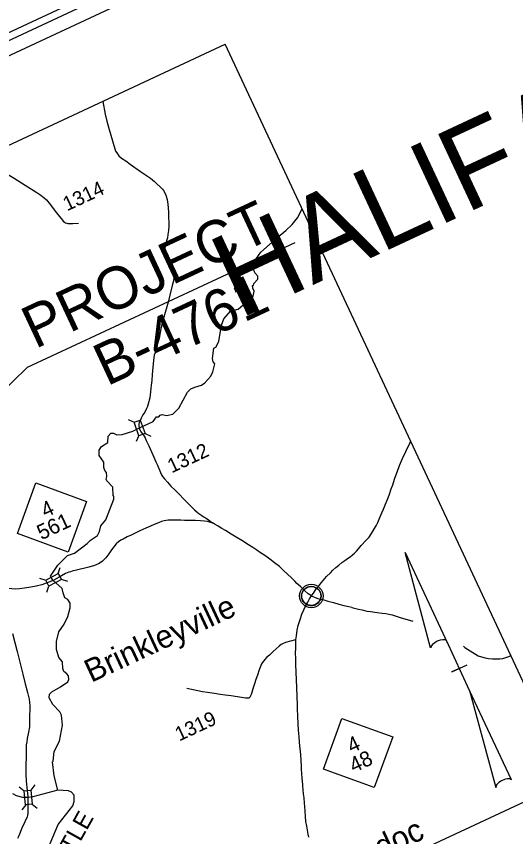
# Model space of a CAD drawing. Extents: x 2318983 to 2324558, y 920396 to 924651.
# Drawn here: x 2320803 to 2321231, y 922780 to 923483 of the extents above; entities that cross this region are included whole.
import ezdxf

# ---------------------------------------------------------------- set-up
doc = ezdxf.new("R2010")
doc.units = 0
for name, color, linetype in [('Default', 7, 'Continuous'), ('Exist Civil Demographics City Label', 7, 'Continuous'), ('Exist Civil Demographics Community CELL', 7, 'Continuous'), ('Exist Hydrographic Creek Single Shore', 7, 'Continuous'), ('Exist Road Primary NC Attributed', 7, 'Continuous'), ('Exist Road Primary NC Shield CELL', 7, 'Continuous'), ('Exist Road Primary NC Shield Number Label', 7, 'Continuous'), ('Exist Road Primary NC Structure Standard Bridge CELL', 7, 'Continuous'), ('Exist Road Secondary Structure Standard Bridge CELL', 7, 'Continuous'), ('Exist Road Secondary Type 20 Attributed', 7, 'Continuous'), ('Exist Road Secondary Type 41 Attributed', 7, 'Continuous'), ('Exist Road Secondary Type 51 Attributed', 7, 'Continuous'), ('Exist Road Secondary Type 51 Number Label', 7, 'Continuous'), ('Pattern 3', 7, 'Continuous'), ('Prop North Arrow for Plan Sheets CELL', 7, 'Continuous'), ('Sheet Data Field CELL', 7, 'Continuous'), ('Sheet Plot Border Inside CELL', 7, 'Continuous'), ('Sheet Title CELL', 7, 'Continuous')]:
    doc.layers.add(name, color=color, linetype=linetype)

msp = doc.modelspace()

# ---------------------------------------------------------------- linework, layer by layer
at = {"layer": 'Exist Civil Demographics Community CELL'}
msp.add_lwpolyline([(2321047.37, 922987.36), (2321047.47, 922987.95), (2321047.66, 922988.65), (2321047.97, 922989.42), (2321048.28, 922990.03), (2321048.64, 922990.64), (2321049.03, 922991.18), (2321049.46, 922991.65), (2321049.94, 922992.14), (2321050.53, 922992.62), (2321051.11, 922993.01), (2321051.63, 922993.32), (2321052.17, 922993.58), (2321052.75, 922993.82), (2321053.34, 922994.02), (2321053.8, 922994.14), (2321054.32, 922994.22), (2321054.76, 922994.29), (2321055.43, 922994.32), (2321055.91, 922994.31), (2321056.51, 922994.28), (2321057.03, 922994.21), (2321057.55, 922994.1), (2321058.08, 922993.95), (2321058.63, 922993.74), (2321059.34, 922993.43), (2321060, 922993.06), (2321060.54, 922992.69), (2321061.09, 922992.26), (2321061.44, 922991.93), (2321061.88, 922991.46), (2321062.29, 922990.96), (2321062.62, 922990.47), (2321062.95, 922989.94), (2321063.21, 922989.39), (2321063.43, 922988.86), (2321063.6, 922988.33), (2321063.73, 922987.84), (2321063.85, 922987.2), (2321063.91, 922986.7), (2321063.94, 922986.06), (2321063.92, 922985.44), (2321063.86, 922984.84), (2321063.76, 922984.26), (2321063.59, 922983.6), (2321063.39, 922982.98), (2321063.14, 922982.44), (2321062.81, 922981.8), (2321062.46, 922981.24), (2321062.09, 922980.74), (2321061.64, 922980.23), (2321061.08, 922979.71), (2321060.55, 922979.27), (2321060.02, 922978.9), (2321059.56, 922978.64), (2321058.83, 922978.29), (2321058.07, 922978.01), (2321057.44, 922977.85), (2321056.74, 922977.71), (2321056.27, 922977.66), (2321055.79, 922977.63), (2321055.2, 922977.63), (2321054.74, 922977.68), (2321054.14, 922977.76), (2321053.51, 922977.89), (2321053.03, 922978.03), (2321052.48, 922978.23), (2321051.99, 922978.44), (2321051.57, 922978.68), (2321050.85, 922979.11), (2321050.26, 922979.57), (2321049.73, 922980.05), (2321049.26, 922980.56), (2321048.92, 922980.98), (2321048.61, 922981.43), (2321048.17, 922982.18), (2321047.99, 922982.56), (2321047.8, 922982.99), (2321047.53, 922983.86), (2321047.37, 922984.61), (2321047.29, 922985.15), (2321047.26, 922985.83), (2321047.25, 922986.32), (2321047.31, 922987.01)], close=True, dxfattribs=at)
for centre, radius in [((2321055.62, 922986.04), 10.03), ((2321055.59, 922986.07), 8.15)]:
    msp.add_circle(centre, radius, dxfattribs=at)
at = {"layer": 'Exist Hydrographic Creek Single Shore'}
for points in [[(2321006.2, 923272.57), (2321012.45, 923281.07), (2321027.04, 923294.35), (2321033.75, 923299.55), (2321039.22, 923304.94), (2321043.67, 923310.54), (2321047.65, 923318.13), (2321047.69, 923318.3)], [(2321006.03, 923252.46), (2321006.2, 923254.32), (2321009.87, 923257.87), (2321009.81, 923260.53), (2321007.13, 923263.33), (2321005.63, 923267.22), (2321006.2, 923272.57)], [(2320972.05, 923198.57), (2320973.65, 923199.6), (2320976.25, 923204.56), (2320978.57, 923218.3), (2320980.54, 923223.87), (2320986.42, 923230.33), (2320992.74, 923232.04), (2321005.73, 923243.24), (2321006.49, 923247.55), (2321005.44, 923250.17), (2321005.21, 923252.42), (2321006.03, 923252.46)], [(2320955.83, 923165.36), (2320961.35, 923167.04), (2320964.2, 923168.93), (2320969.46, 923174.56), (2320971.26, 923178.43), (2320972.81, 923185.27), (2320971.36, 923187.07), (2320970.92, 923189.72), (2320972.05, 923198.57)], [(2320924.98, 923139.78), (2320925.99, 923141.19), (2320927.62, 923141.67), (2320931.53, 923140.86), (2320936.84, 923141.96), (2320941.91, 923147.34), (2320949.31, 923160.81), (2320952.17, 923163.91), (2320955.83, 923165.36)], [(2320902.99, 923127.65), (2320908.3, 923130.23), (2320919.91, 923135.86), (2320922.94, 923139.78), (2320924.98, 923139.78)], [(2320879.71, 923086.24), (2320880.11, 923088.67), (2320879.86, 923091.97), (2320878.41, 923093.61), (2320877.77, 923096.41), (2320877.72, 923100.93), (2320873.56, 923106.65), (2320873.71, 923111.19), (2320875.72, 923114.26), (2320881.21, 923117.79), (2320881.36, 923123.13), (2320883.79, 923125.81), (2320885.84, 923125.65), (2320888.94, 923124.25), (2320893.44, 923124.67), (2320902.5, 923127.5), (2320902.99, 923127.65)], [(2320863.5, 923031.14), (2320866.13, 923033.99), (2320872.23, 923037.96), (2320874.05, 923041.5), (2320875.01, 923046.23), (2320879.49, 923051.34), (2320886.26, 923069.06), (2320886.23, 923071.56), (2320885.62, 923072.1), (2320885.32, 923079.52), (2320880.35, 923084.81), (2320879.71, 923086.24)], [(2320846.06, 922919.22), (2320843.37, 922921.2), (2320842.51, 922923.68), (2320842.24, 922929.64), (2320839.14, 922933.31), (2320837.22, 922940.01), (2320837.15, 922947.03), (2320839.09, 922955.19), (2320843.54, 922961.83), (2320846.74, 922968.43), (2320848.93, 922975.78), (2320848.69, 922979.73), (2320846.79, 922982.97), (2320844.33, 922984.56), (2320842.83, 922988.86), (2320841.96, 922992.39), (2320834.03, 922999.56), (2320832.05, 923002.92), (2320838.28, 923012.42), (2320846.4, 923020.9), (2320852.53, 923022.77), (2320863.5, 923031.14)], [(2320834.15, 922844.27), (2320835.08, 922852.47), (2320839.71, 922861.54), (2320842.22, 922875.29), (2320841.31, 922883.89), (2320839.83, 922886.58), (2320834.02, 922892.88), (2320830.9, 922898.73), (2320831.07, 922901.64), (2320833.09, 922903.9), (2320840.64, 922908.09), (2320846.74, 922912.46), (2320847.73, 922914.36), (2320847.51, 922917.58), (2320846.06, 922919.22)], [(2320838.11, 922819.31), (2320835.08, 922831.79), (2320833.73, 922843.69), (2320834.15, 922844.27)], [(2320838.11, 922819.31), (2320816.88, 922813.61), (2320814.92, 922813.32), (2320812.16, 922813.1), (2320809.89, 922812.97), (2320808.25, 922813.16), (2320802.9, 922814.4), (2320799.61, 922816.28)], [(2320820.96, 922750.14), (2320821.58, 922753.55), (2320828.2, 922767.39), (2320829.43, 922768.16), (2320838.41, 922790.01), (2320851.15, 922805.96), (2320852.36, 922809.81), (2320852.28, 922814.97), (2320850.02, 922817.62), (2320847.34, 922818.97), (2320838.11, 922819.31)]]:
    msp.add_lwpolyline(points, dxfattribs=at)
at = {"layer": 'Exist Road Primary NC Attributed'}
for points in [[(2321055.62, 922986.04), (2321056.73, 922987.45), (2321058.13, 922989.43), (2321059.79, 922992.04), (2321062.29, 922994.99), (2321064.24, 922997.56), (2321065.83, 922999.45), (2321067.09, 923001.07), (2321068.66, 923002.8), (2321071.95, 923005.91), (2321074.05, 923008.07), (2321076.56, 923010.34), (2321079.08, 923012.5), (2321081.83, 923014.9), (2321084.47, 923016.56), (2321086.67, 923018.06), (2321088.91, 923019.71), (2321090.81, 923021.21), (2321092.71, 923022.86), (2321094.31, 923024.55), (2321096.06, 923026.49), (2321098.48, 923029.27), (2321102.71, 923033.9), (2321105.13, 923036.64), (2321107.11, 923039.61), (2321109.67, 923043.87), (2321111.46, 923046.94), (2321112.61, 923049.17), (2321114.33, 923053.27), (2321116.15, 923057.28), (2321117.49, 923060.44), (2321119.3, 923064.85), (2321120.73, 923068.14), (2321122.35, 923072.64), (2321122.63, 923073.47), (2321124.14, 923077.91), (2321125.51, 923081.35), (2321127.02, 923086.24), (2321128.17, 923089.47), (2321129.4, 923093.11), (2321131.36, 923097.95), (2321133.92, 923104.11), (2321136.71, 923110.07), (2321139.95, 923117.08), (2321140.84, 923118.7)], [(2320971.51, 923048.64), (2320968.21, 923049.45), (2320966.48, 923049.92), (2320963.93, 923050.14), (2320960.68, 923050.49), (2320956.19, 923050.78), (2320951.42, 923050.87), (2320946.89, 923050.91), (2320943.59, 923051.02), (2320935.92, 923051.23), (2320932.73, 923051.09), (2320929.53, 923050.56), (2320927.23, 923049.94), (2320924.49, 923048.78), (2320920.96, 923047.36), (2320917.68, 923045.89), (2320913.72, 923044.17), (2320908.63, 923041.89), (2320903.5, 923039.45), (2320901.05, 923038.29), (2320897.81, 923036.85), (2320894.34, 923034.92), (2320892.12, 923033.93), (2320890.17, 923032.5), (2320888.3, 923030.78), (2320884.25, 923025.76), (2320881.89, 923022.1), (2320879.27, 923018.82), (2320876.6, 923015.89), (2320874.55, 923014.54), (2320873.03, 923013.58), (2320871.74, 923013.05), (2320869.57, 923012.23), (2320864.93, 923010.88), (2320854.29, 923008.14), (2320850.47, 923007.24), (2320848.97, 923006.79), (2320847.78, 923006.49), (2320844.86, 923005.37), (2320839.39, 923002.3), (2320834.67, 922999.67), (2320831.33, 922998.26)], [(2321055.62, 922986.04), (2321054.37, 922986.91), (2321053.01, 922987.94), (2321049.8, 922990.66), (2321046.51, 922993.77), (2321043.28, 922996.83), (2321041.34, 922998.77), (2321039.65, 923000.38), (2321038.25, 923001.84), (2321035.56, 923004.46), (2321031.54, 923008.3), (2321028.2, 923011.31), (2321024.13, 923014.51), (2321020.11, 923017.7), (2321017.67, 923019.39), (2321014.95, 923021.28), (2321012.07, 923023.17), (2321008.95, 923025.34), (2321005.57, 923027.52), (2321001.66, 923029.93), (2320995.91, 923033.55), (2320991.1, 923036.59), (2320986.93, 923039.2), (2320982.08, 923042.14), (2320978.81, 923044.07), (2320975.68, 923045.9), (2320973.16, 923047.49), (2320971.51, 923048.64)], [(2320831.33, 922998.26), (2320828.3, 922996.98), (2320824.41, 922995.55), (2320819.54, 922994.43), (2320815.04, 922993.68), (2320809.58, 922992.78), (2320805.23, 922992.03), (2320801.71, 922991.95), (2320796.02, 922992.33), (2320789.45, 922992.87)], [(2321042.39, 922948.31), (2321042.84, 922951.86), (2321043.57, 922956.64), (2321044.31, 922960.68), (2321045.06, 922963.35), (2321046.2, 922966.85), (2321047.54, 922970.32), (2321049.26, 922974.27), (2321050.75, 922977.39), (2321052.48, 922980.85), (2321054.08, 922983.62), (2321055.62, 922986.04)], [(2321055.62, 922986.04), (2321056.79, 922985.6), (2321058.29, 922985.02), (2321060.26, 922984.29), (2321063.17, 922983.44), (2321066.43, 922982.59), (2321069.83, 922981.7), (2321074.67, 922980.33), (2321079.06, 922979.15), (2321083.4, 922977.98), (2321087.76, 922977.04), (2321090.34, 922976.32), (2321090.27, 922976.24), (2321092.63, 922975.63), (2321096.19, 922974.74), (2321099.35, 922974.04), (2321103.24, 922973.15), (2321106.4, 922972.6), (2321111.96, 922971.78), (2321116.45, 922971.24), (2321119.55, 922970.89), (2321122.22, 922970.33), (2321124.83, 922969.72), (2321131.79, 922967.49), (2321142.65, 922964.35)], [(2321053.38, 922779.17), (2321052.78, 922781.53), (2321051.64, 922788.44), (2321051, 922792.62), (2321050.61, 922796.75), (2321050.29, 922801.25), (2321050.03, 922805.27), (2321049.83, 922808.14), (2321049.33, 922812.76), (2321048.95, 922816.22), (2321048.56, 922819.64), (2321048.27, 922823.09), (2321048.24, 922824.16), (2321047.85, 922829.62), (2321047.61, 922833.61), (2321047.32, 922837.09), (2321047.19, 922839.75), (2321046.8, 922845.23), (2321046.5, 922849.6), (2321046.22, 922852.82), (2321045.88, 922857.07), (2321045.54, 922860.96), (2321045.23, 922865.28), (2321044.71, 922870.96), (2321044.36, 922876.42), (2321044.1, 922882.99), (2321043.88, 922889.19), (2321043.88, 922893.04), (2321043.44, 922899.55), (2321043.07, 922907.69), (2321042.95, 922913.74), (2321042.67, 922921.01), (2321042.45, 922926.87), (2321042.38, 922932.42), (2321042.18, 922937), (2321042.23, 922941.18), (2321042.27, 922945.71), (2321042.39, 922948.31)], [(2321186.11, 922942.87), (2321187.16, 922941.93), (2321198.61, 922934.79), (2321201.42, 922933.89), (2321204.63, 922932.95), (2321207.64, 922932.49), (2321211.04, 922932.09), (2321212.78, 922931.98), (2321214.38, 922931.98), (2321214.87, 922932.04), (2321217.14, 922932.06), (2321219.84, 922932.39), (2321222.39, 922933.21), (2321224.93, 922934.13), (2321226.6, 922934.95)]]:
    msp.add_lwpolyline(points, dxfattribs=at)
at = {"layer": 'Exist Road Primary NC Shield CELL'}
for p, q in [((2320803.5, 923039.53), (2320819.34, 923083.09)), ((2320819.34, 923083.09), (2320862.9, 923067.25)), ((2320862.9, 923067.25), (2320847.06, 923023.7)), ((2320847.06, 923023.7), (2320803.5, 923039.53)), ((2321066.06, 922837.39), (2321081.9, 922880.95)), ((2321081.9, 922880.95), (2321125.46, 922865.11)), ((2321125.46, 922865.11), (2321109.62, 922821.55)), ((2321109.62, 922821.55), (2321066.06, 922837.39))]:
    msp.add_line(p, q, dxfattribs=at)
at = {"layer": 'Exist Road Primary NC Structure Standard Bridge CELL'}
for p, q in [((2320838.6, 923005.31), (2320840.25, 923010.62)), ((2320822.48, 923001.3), (2320827.8, 922999.65)), ((2320841.2, 923000.38), (2320846.52, 922998.73)), ((2320828.8, 922989.28), (2320830.45, 922994.6))]:
    msp.add_line(p, q, dxfattribs=at)
msp.add_lwpolyline([(2320827.8, 922999.65), (2320838.59, 923005.33), (2320841.24, 923000.29), (2320830.45, 922994.6)], close=True, dxfattribs=at)
at = {"layer": 'Exist Road Secondary Structure Standard Bridge CELL'}
for p, q in [((2320911.35, 923142.05), (2320908.97, 923137.01)), ((2320898.57, 923137.48), (2320903.6, 923135.1)), ((2320907.8, 923123.64), (2320905.42, 923118.61)), ((2320913.05, 923125.52), (2320918.08, 923123.13)), ((2320818.45, 922823.84), (2320814.97, 922819.5)), ((2320804.96, 922822.36), (2320809.3, 922818.88)), ((2320810.73, 922806.77), (2320807.25, 922802.42)), ((2320816.27, 922807.37), (2320820.61, 922803.89))]:
    msp.add_line(p, q, dxfattribs=at)
for points in [[(2320908.97, 923137.01), (2320913.07, 923125.53), (2320907.71, 923123.61), (2320903.6, 923135.1)], [(2320814.97, 922819.5), (2320816.3, 922807.37), (2320810.63, 922806.75), (2320809.3, 922818.88)]]:
    msp.add_lwpolyline(points, close=True, dxfattribs=at)
at = {"layer": 'Exist Road Secondary Type 20 Attributed'}
msp.add_lwpolyline([(2321042.39, 922948.31), (2321040.8, 922948.13), (2321038.92, 922947.69), (2321036.57, 922946.99), (2321034.52, 922946.43), (2321033.51, 922945.99), (2321030.94, 922944.94), (2321029.69, 922944.31), (2321027.92, 922942.93), (2321025.51, 922940.63), (2321022.91, 922938.32), (2321019.68, 922935.35), (2321017.19, 922933.13), (2321015.66, 922931.55), (2321014.53, 922930.24), (2321013.39, 922928.58), (2321012.69, 922927.36), (2321011.91, 922925.53), (2321010.77, 922922.64), (2321009.33, 922918.06), (2321008.11, 922914.39), (2321006.89, 922910.63), (2321005.45, 922906.38), (2321004.53, 922903.19), (2321003.92, 922901.48), (2321003.46, 922900.22), (2321003.08, 922899.48), (2321002.64, 922898.89), (2321002.26, 922898.45), (2321001.74, 922898.27), (2321000.6, 922898.34), (2320999.03, 922898.43), (2320992.44, 922899.43), (2320990.28, 922899.83), (2320986.81, 922900.29), (2320981.84, 922900.95), (2320977.38, 922901.6), (2320972.54, 922902.36), (2320966.52, 922903.08), (2320962.2, 922903.86), (2320954.41, 922905.37), (2320948.84, 922906.62)], dxfattribs=at)
at = {"layer": 'Exist Road Secondary Type 41 Attributed'}
msp.add_lwpolyline([(2320876.8, 923410.5), (2320878.78, 923399.48), (2320880.34, 923393.61), (2320882.36, 923386.46), (2320885.01, 923376.74), (2320887.76, 923367.85), (2320888.71, 923366.25), (2320890.66, 923363.62), (2320892.89, 923361.77), (2320896.65, 923359.37), (2320900.27, 923356.61), (2320909.16, 923350.16), (2320913.52, 923347.34), (2320917.62, 923344.45), (2320921.06, 923341.75), (2320927.98, 923335.23), (2320928.87, 923334.11), (2320930.38, 923331.56), (2320930.93, 923329.97), (2320931.98, 923326.16), (2320932.46, 923322.34), (2320932.99, 923315.61), (2320933.25, 923310.25), (2320933.45, 923307.29), (2320933.28, 923303.34), (2320933, 923299.67), (2320932.66, 923296.12), (2320932.15, 923293.24), (2320931.53, 923290.7), (2320930.91, 923288.33), (2320929.59, 923283.5), (2320929.11, 923281.05), (2320929.11, 923279.59), (2320929.33, 923277.84), (2320930.22, 923275.58), (2320931.42, 923273.35), (2320932.83, 923270.98), (2320936.55, 923265.76), (2320937.4, 923263.53), (2320937.73, 923261.76), (2320937.79, 923261.28), (2320937.74, 923259.27), (2320937.28, 923256.45), (2320936.27, 923252.45), (2320934.3, 923244.32), (2320932.72, 923238.23), (2320929.11, 923225.36), (2320927.47, 923218.99), (2320926.68, 923215.15), (2320925.24, 923207.14), (2320923.13, 923200.31), (2320921.84, 923195.68), (2320920.88, 923192.61), (2320920.2, 923188.32), (2320919.13, 923176.13), (2320918.84, 923170.91), (2320918.28, 923166.91), (2320917.66, 923161.09), (2320917.27, 923158.61), (2320916.99, 923156.07), (2320916.61, 923154.18), (2320916.25, 923152.8), (2320915.01, 923148.62), (2320914.29, 923146.85), (2320912.7, 923143.83), (2320911.18, 923141.4), (2320909.68, 923138.57), (2320907.91, 923135), (2320907.57, 923133.59), (2320907.69, 923132.11), (2320908.26, 923129.26)], dxfattribs=at)
at = {"layer": 'Exist Road Secondary Type 51 Attributed'}
for points in [[(2320793.54, 923348.78), (2320800.65, 923344.5), (2320810.3, 923338.55), (2320820.15, 923332.15), (2320823.7, 923329.91), (2320826.63, 923327.79), (2320828.46, 923326.12), (2320830.86, 923323.06), (2320837.01, 923314.83), (2320842.14, 923308.51), (2320842.92, 923307.62), (2320843.98, 923306.8), (2320844.75, 923306.31), (2320846.05, 923305.87), (2320846.79, 923305.74), (2320848.21, 923305.7), (2320851.1, 923305.7), (2320855.87, 923305.87)], [(2320817.04, 923334.18), (2320820.15, 923332.15), (2320823.7, 923329.91), (2320826.63, 923327.79), (2320828.46, 923326.12), (2320830.86, 923323.06), (2320837.01, 923314.83), (2320842.14, 923308.51), (2320842.92, 923307.62), (2320843.98, 923306.8), (2320844.75, 923306.31), (2320846.05, 923305.87), (2320846.79, 923305.74), (2320848.21, 923305.7), (2320851.1, 923305.7), (2320855.87, 923305.87)], [(2320908.26, 923129.26), (2320909.71, 923126.7), (2320911.63, 923123.94), (2320912.7, 923122.19), (2320912.74, 923122.11)], [(2320912.7, 923122.19), (2320914.05, 923119.54), (2320916.31, 923114.94), (2320919.69, 923107.24), (2320922.34, 923101.2), (2320923.58, 923098.38), (2320926.18, 923091.94), (2320927.02, 923090.08), (2320928.09, 923088.45), (2320929.62, 923086.53), (2320932.13, 923083.7), (2320935.2, 923080.41), (2320938.91, 923076.79), (2320942.05, 923073.63), (2320946.42, 923069.09), (2320950.87, 923064.44), (2320955.33, 923060.04), (2320957.78, 923057.93), (2320959.16, 923056.88), (2320961.78, 923055.07), (2320963.81, 923053.8), (2320964.86, 923053.14), (2320967.03, 923051.77), (2320968.97, 923050.33), (2320971.51, 923048.64)], [(2320799.33, 922953.77), (2320803.38, 922938.26), (2320806.13, 922926.86), (2320808.12, 922919.07), (2320810.22, 922910.57), (2320812.12, 922903.13), (2320813.62, 922897.53), (2320814.26, 922891.88), (2320814.11, 922888.49), (2320814.01, 922883.49), (2320814.06, 922876.09), (2320813.91, 922873.69), (2320813.07, 922869.2), (2320812.02, 922863.65), (2320811.52, 922860.9), (2320811.17, 922858.4), (2320810.97, 922856.5), (2320810.97, 922849.06), (2320810.77, 922839.66), (2320810.87, 922833.04), (2320811.19, 922827.18), (2320811.8, 922819.09), (2320812.52, 922814.14)], [(2320812.52, 922814.14), (2320812.6, 922802.18), (2320812.52, 922799.59), (2320812.27, 922797.61), (2320811.92, 922796.41), (2320809.97, 922792.32), (2320807.42, 922786.82), (2320804.83, 922780.32), (2320803.63, 922777.88)]]:
    msp.add_lwpolyline(points, dxfattribs=at)
at = {"layer": 'Pattern 3'}
for p, q in [((2320106.71, 923051.1), (2320981.79, 923459.5)), ((2321276.76, 922827.48), (2320981.79, 923459.5)), ((2320812.16, 923182.33), (2321041.74, 923289.48)), ((2320812.16, 923182.33), (2320687.87, 923062.03))]:
    msp.add_line(p, q, dxfattribs=at)
msp.add_lwpolyline([(2320401.68, 922419.08), (2321276.76, 922827.48), (2321342.28, 922687.08), (2320467.2, 922278.68)], close=True, dxfattribs=at)
at = {"layer": 'Prop North Arrow for Plan Sheets CELL'}
for p, q in [((2321136.11, 923023.49), (2321136.03, 923023.45)), ((2321136.11, 923023.49), (2321136.03, 923023.45)), ((2321157.94, 922941.61), (2321136.03, 923023.45)), ((2321136.11, 923023.49), (2321172.5, 922945.52)), ((2321191.38, 922905.07), (2321171.44, 922947.81)), ((2321172.5, 922945.52), (2321171.47, 922947.73)), ((2321181.82, 922923.65), (2321176.03, 922920.95)), ((2321176.11, 922920.99), (2321189.16, 922927.08)), ((2321176.03, 922920.95), (2321175.94, 922920.91)), ((2321191.38, 922905.07), (2321213.73, 922821.65)), ((2321227.28, 922828.37), (2321191.38, 922905.07))]:
    msp.add_line(p, q, dxfattribs=at)
for centre, start_param, end_param in [((2321165.07, 922943.95), 0.216388, 2.908219), ((2321220.77, 922824.6), 0.201328, 3.141593)]:
    msp.add_ellipse(centre, major_axis=(6.92, 3.17), ratio=0.461098, start_param=start_param, end_param=end_param, dxfattribs=at)
at = {"layer": 'Sheet Plot Border Inside CELL'}
msp.add_lwpolyline([(2320660.3, 920611.69), (2324284.61, 922303.17), (2323213.7, 924597.81), (2319589.38, 922906.33)], close=True, dxfattribs=at)
at = {"layer": 'Sheet Title CELL'}
for points in [[(2323167.38, 924569.44), (2319948.6, 923067.25)], [(2323161.55, 924553.48), (2320073.35, 923112.2)]]:
    msp.add_lwpolyline(points, dxfattribs=at)

# ---------------------------------------------------------------- texts
at = {"layer": 'Default'}
msp.add_text('LITTLE', height=14.881, rotation=60.89969, dxfattribs=at).set_placement((2320837.69, 922738.86))
at = {"layer": 'Exist Civil Demographics City Label'}
for s, p in [('Brinkleyville', (2320866.88, 922911.41)), ('Medoc', (2321082.35, 922744.9))]:
    msp.add_text(s, height=19.683, rotation=25.01869, dxfattribs=at).set_placement(p)
at = {"layer": 'Exist Road Primary NC Shield Number Label'}
for s, p in [('4', (2320827.53, 923052.97)), ('561', (2320824.13, 923033.76)), ('4', (2321090.09, 922850.83)), ('48', (2321091.99, 922834.09))]:
    msp.add_text(s, height=13.04, rotation=25.01869, dxfattribs=at).set_placement(p)
at = {"layer": 'Exist Road Secondary Type 51 Number Label'}
for s, p in [('1314', (2320846.15, 923316.08)), ('1312', (2320935.83, 923091.21)), ('1319', (2320942.26, 922861.09))]:
    msp.add_text(s, height=12.302, rotation=25.01869, dxfattribs=at).set_placement(p)
at = {"layer": 'Pattern 3'}
for s, p in [('PROJECT', (2320818.73, 923197.75)), ('B-4761', (2320880.27, 923165.72))]:
    msp.add_text(s, height=36.3, rotation=25.01875, dxfattribs=at).set_placement(p)
at = {"layer": 'Sheet Data Field CELL'}
msp.add_text('        HALIFAX COUNTY       ', height=72, rotation=25.01869, dxfattribs=at).set_placement((2320799.83, 923132.8))

doc.saveas('drawing.dxf')
